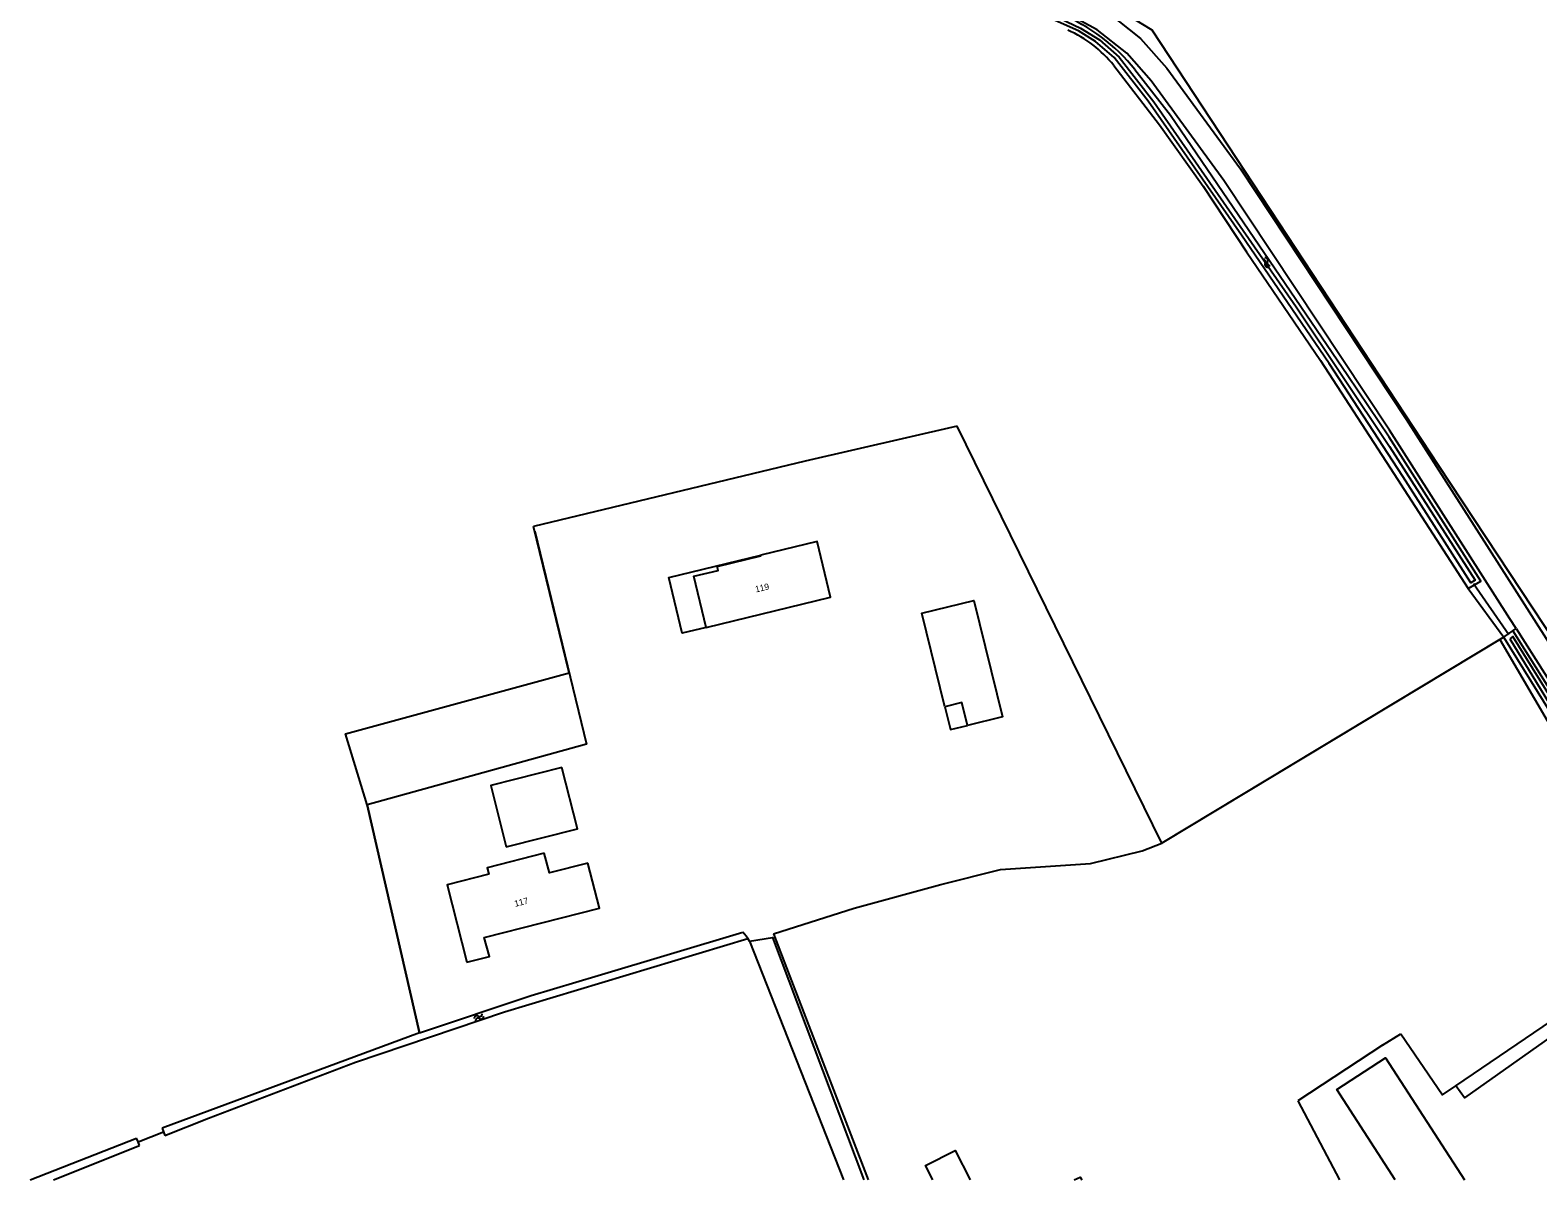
# Model space of a CAD drawing. Extents: x 137000 to 140001, y 403500 to 406000.
# Drawn here: x 138676.6 to 138915.5, y 403500 to 403682.2 of the extents above; entities that cross this region are included whole.
import ezdxf

# ---------------------------------------------------------------- set-up
doc = ezdxf.new("R2010")
doc.units = 0
for name, color, linetype in [('gg-afsc-draadraster', 7, 'Continuous'), ('gg-afsc-lijn draadraster', 7, 'Continuous'), ('gg-anno-huisnummerreeks BGT', 7, 'Continuous'), ('gg-bbg-bijgebouw', 7, 'Continuous'), ('gg-bbg-bijgebouw onder overbouw', 7, 'Continuous'), ('gg-bbg-gedigitaliseerde bebouwing', 7, 'Continuous'), ('gg-bbg-gedigitaliseerde bijgebouw', 7, 'Continuous'), ('gg-bbg-hoofdgebouw', 7, 'Continuous'), ('gg-bbg-luifel en loopbrug', 7, 'Continuous'), ('gg-bbg-pand overbouw', 7, 'Continuous'), ('gg-knt-bronhoudergrens', 7, 'Continuous'), ('gg-knt-onverhard', 7, 'Continuous'), ('gg-kntw-bovenkant insteek waterloop', 7, 'Continuous'), ('gg-kntw-waterlijn', 7, 'Continuous'), ('gg-kwrk-duiker nz buis', 7, 'Continuous'), ('gt-grn-groengrens', 7, 'Continuous'), ('gt-symb-watersymbool', 7, 'Continuous')]:
    doc.layers.add(name, color=color, linetype=linetype)

# ---------------------------------------------------------------- blocks, each defined once
blk = doc.blocks.new('gt0-WA')
at = {"layer": 'gt-symb-watersymbool'}
for centre, start, end in [((-0.32, 0.02), 28.0725, 151.9275), ((0.43, 0.42), 208.0725, 331.9275), ((-0.32, -0.43), 28.0725, 151.9275), ((0.43, -0.03), 208.0725, 331.9275)]:
    blk.add_arc(centre, 0.425, start, end, dxfattribs=at)

msp = doc.modelspace()

# ---------------------------------------------------------------- linework, layer by layer
at = {"layer": 'gg-afsc-draadraster'}
for p, q in [((138855.93, 403553.34), (138823.51, 403619.47)), ((138890.89, 403521.33), (138893.81, 403523.12)), ((138890.89, 403521.33), (138877.5, 403512.54)), ((138877.5, 403512.54), (138884.07, 403500))]:
    msp.add_line(p, q, dxfattribs=at)
for points in [[(138823.51, 403619.47), (138799.39, 403613.89), (138756.35, 403603.56)], [(138909.53, 403585.64), (138929.1, 403552.08), (138945.69, 403522.32), (138947.51, 403519.82), (138962.83, 403500)], [(138794.39, 403539.01), (138807.19, 403543.04), (138820.91, 403546.8), (138830.35, 403549.2), (138844.62, 403550.14), (138852.81, 403552.15), (138855.93, 403553.34)], [(138794.39, 403539.01), (138796.45, 403533.62), (138809.4, 403500)], [(138893.81, 403523.12), (138900.4, 403513.46), (138902.52, 403514.91)]]:
    msp.add_lwpolyline(points, dxfattribs=at)
at = {"layer": 'gg-afsc-lijn draadraster'}
for p, q in [((138855.93, 403553.34), (138823.51, 403619.47)), ((138756.55, 403602.78), (138764.76, 403569.05)), ((138904.5, 403593.73), (138910.14, 403586.01)), ((138910.14, 403586.01), (138855.93, 403553.34))]:
    msp.add_line(p, q, dxfattribs=at)
for points in [[(138823.51, 403619.47), (138799.39, 403613.89), (138756.35, 403603.56)], [(138764.76, 403569.05), (138729.97, 403559.45), (138738.28, 403523.29)], [(138794.39, 403539.01), (138807.19, 403543.04), (138820.91, 403546.8), (138830.35, 403549.2), (138844.62, 403550.14), (138852.81, 403552.15), (138855.93, 403553.34)]]:
    msp.add_lwpolyline(points, dxfattribs=at)
at = {"layer": 'gg-bbg-bijgebouw'}
for points in [[(138821.56, 403574.98), (138817.92, 403589.82), (138826.13, 403591.84), (138830.67, 403573.38), (138825.13, 403572.02)], [(138752.03, 403552.77), (138763.3, 403555.61), (138760.85, 403565.35)]]:
    msp.add_lwpolyline(points, dxfattribs=at)
at = {"layer": 'gg-bbg-bijgebouw onder overbouw'}
msp.add_lwpolyline([(138825.13, 403572.02), (138824.24, 403575.64), (138821.56, 403574.98)], dxfattribs=at)
at = {"layer": 'gg-bbg-gedigitaliseerde bebouwing'}
msp.add_lwpolyline([(138758.05, 403551.76), (138748.99, 403549.45), (138749.25, 403548.43), (138742.67, 403546.77), (138745.78, 403534.5)], dxfattribs=at)
at = {"layer": 'gg-bbg-gedigitaliseerde bijgebouw'}
for points in [[(138760.85, 403565.35), (138749.58, 403562.51), (138752.03, 403552.77)], [(138892.93, 403500), (138883.65, 403514.33), (138891.39, 403519.35), (138903.9, 403500)]]:
    msp.add_lwpolyline(points, dxfattribs=at)
at = {"layer": 'gg-bbg-hoofdgebouw'}
for points in [[(138783.72, 403587.56), (138803.42, 403592.34), (138801.3, 403601.15), (138792.36, 403598.99)], [(138783.72, 403587.56), (138781.75, 403595.65), (138785.62, 403596.59), (138785.47, 403597.22), (138792.38, 403598.9), (138792.36, 403598.99)], [(138764.97, 403550.2), (138758.87, 403548.64), (138758.05, 403551.76)], [(138745.78, 403534.5), (138749.37, 403535.38), (138748.53, 403538.41), (138766.83, 403543.03), (138764.97, 403550.2)]]:
    msp.add_lwpolyline(points, dxfattribs=at)
at = {"layer": 'gg-bbg-luifel en loopbrug'}
msp.add_lwpolyline([(138783.72, 403587.56), (138779.93, 403586.64), (138777.79, 403595.46), (138792.36, 403598.99)], dxfattribs=at)
at = {"layer": 'gg-bbg-pand overbouw'}
msp.add_lwpolyline([(138821.56, 403574.98), (138822.45, 403571.36), (138825.13, 403572.02)], dxfattribs=at)
at = {"layer": 'gg-knt-bronhoudergrens'}
for p, q in [((138904.5, 403593.73), (138910.14, 403586.01)), ((138909.53, 403585.64), (138855.93, 403553.34)), ((138910.14, 403586.01), (138909.53, 403585.64)), ((138693.68, 403506.03), (138697.69, 403507.61))]:
    msp.add_line(p, q, dxfattribs=at)
for points in [[(138927.79, 403570.85), (138899.84, 403613.18), (138854.38, 403682.2), (138839.71, 403691.17), (138830.13, 403698.12), (138829.82, 403702.76), (138839.37, 403702.89), (138846.05, 403702.76), (138855.75, 403705.21), (138868.54, 403712.34), (138936.93, 403749.4)], [(138738.28, 403523.29), (138729.97, 403559.45), (138726.53, 403570.68), (138762.01, 403580.33), (138756.35, 403603.56)], [(138819.64, 403500), (138818.49, 403502.25), (138823.2, 403504.66), (138825.58, 403500)], [(138842.02, 403500), (138843.01, 403500.45), (138843.25, 403500)]]:
    msp.add_lwpolyline(points, dxfattribs=at)
at = {"layer": 'gg-knt-onverhard'}
for q in [(138790.32, 403538.23), (138805.49, 403500)]:
    msp.add_line((138790.6, 403537.8), q, dxfattribs=at)
for points in [[(138763.27, 403791.65), (138796.33, 403740.91), (138812.12, 403718.5), (138829.15, 403696.49), (138832.98, 403692.82), (138847.44, 403684.95), (138852.56, 403680.89), (138856.74, 403676.17), (138868.38, 403660.23), (138894.68, 403620.54), (138913.81, 403590.62), (138923.24, 403575.78)], [(138912.08, 403587.37), (138911.11, 403588.9), (138892, 403618.8), (138865.76, 403658.4), (138854.24, 403674.16), (138850.36, 403678.55), (138845.67, 403682.27), (138831.07, 403690.22), (138826.76, 403694.35), (138809.54, 403716.6), (138793.68, 403739.11), (138766.95, 403780.14)], [(138912.08, 403587.37), (138930.06, 403559.08), (138947.12, 403529.11), (138959.02, 403511.66), (138967.78, 403500)], [(138790.6, 403537.8), (138794.25, 403538.43), (138808.68, 403500)]]:
    msp.add_lwpolyline(points, dxfattribs=at)
at = {"layer": 'gg-kntw-bovenkant insteek waterloop'}
for p, q in [((138910.19, 403585.95), (138910.19, 403586.01)), ((138738.28, 403523.29), (138697.47, 403508.18)), ((138676.57, 403500), (138693.44, 403506.6)), ((138693.68, 403506.03), (138693.44, 403506.6)), ((138697.47, 403508.18), (138697.69, 403507.61)), ((138697.69, 403507.61), (138697.92, 403507.04)), ((138680.25, 403500), (138693.92, 403505.45)), ((138693.92, 403505.45), (138693.68, 403506.03))]:
    msp.add_line(p, q, dxfattribs=at)
for points in [[(138848.31, 403676.62), (138855.56, 403667.18), (138862.47, 403657.48), (138869.35, 403647.08), (138881.08, 403629.85), (138892.12, 403612.84), (138904.5, 403593.73)], [(138904.5, 403593.73), (138906.51, 403594.9), (138891.98, 403617.68), (138885.44, 403627.41), (138857.32, 403668.66), (138851.67, 403675.94)], [(138911.59, 403587.02), (138927.71, 403561.31), (138945.43, 403529.12), (138943.63, 403528.08), (138926.05, 403560.4), (138910.21, 403585.9), (138910.19, 403585.95)], [(138910.19, 403586.01), (138910.2, 403586.05), (138911.59, 403587.02)], [(138697.92, 403507.04), (138704.85, 403509.78), (138728.13, 403518.64), (138751.73, 403526.61), (138790.32, 403538.23)], [(138738.28, 403523.29), (138755.97, 403529.19), (138766.58, 403532.4), (138789.52, 403539.23)], [(138790.32, 403538.23), (138790.07, 403538.6), (138789.52, 403539.23)], [(138902.52, 403514.91), (138917.72, 403525.2), (138933.7, 403536.2), (138934.6, 403534.77), (138916.51, 403521.94)], [(138916.51, 403521.94), (138903.89, 403512.99), (138902.52, 403514.91)]]:
    msp.add_lwpolyline(points, dxfattribs=at)
for centre, radius, start, end in [((138828.93, 403657.8), 29.1, 38.5843, 67.7946), ((138833.58, 403664.99), 18.76, 38.2899, 66.5493)]:
    msp.add_arc(centre, radius, start, end, dxfattribs=at)
at = {"layer": 'gg-kntw-waterlijn'}
for points in [[(138832.22, 403686.83), (138839.82, 403684.06), (138843.06, 403682.52), (138846.04, 403680.68), (138849.15, 403677.91), (138854.67, 403670.84), (138877.22, 403638.38), (138892, 403616.23), (138905.58, 403595.04), (138904.92, 403594.61), (138894.11, 403611.48), (138882.43, 403629.35), (138868.57, 403649.71), (138853.77, 403670.93), (138848.37, 403677.85), (138845.42, 403680.42), (138842.71, 403682.11), (138839.02, 403683.71), (138831.91, 403686.23), (138832.22, 403686.83)], [(138911.08, 403585.72), (138927.43, 403559.01), (138943.82, 403528.94), (138944.29, 403529.2), (138934.78, 403546.66), (138927.43, 403560.6), (138911.58, 403586.11), (138911.08, 403585.72)]]:
    msp.add_lwpolyline(points, dxfattribs=at)
at = {"layer": 'gg-kwrk-duiker nz buis'}
msp.add_line((138910.94, 403586.38), (138905.31, 403594.46), dxfattribs=at)
at = {"layer": 'gt-grn-groengrens'}
for p, q in [((138911.59, 403587.02), (138912.08, 403587.37)), ((138910.14, 403586.01), (138910.19, 403585.95))]:
    msp.add_line(p, q, dxfattribs=at)

# ---------------------------------------------------------------- block references
at = {"layer": 'gt-symb-watersymbool'}
for p, rotation in [((138872.53, 403645.34), 124.73862528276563), ((138747.74, 403525.77), -149.4095645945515)]:
    msp.add_blockref('gt0-WA', p, dxfattribs=dict(at, rotation=rotation))

# ---------------------------------------------------------------- texts
at = {"layer": 'gg-anno-huisnummerreeks BGT'}
for s, rotation, p in [('119', 13.6, (138791.61, 403593.08)), ('117', 14.2, (138753.45, 403543.26))]:
    msp.add_text(s, height=1, rotation=rotation, dxfattribs=at).set_placement(p)

doc.saveas('drawing.dxf')
